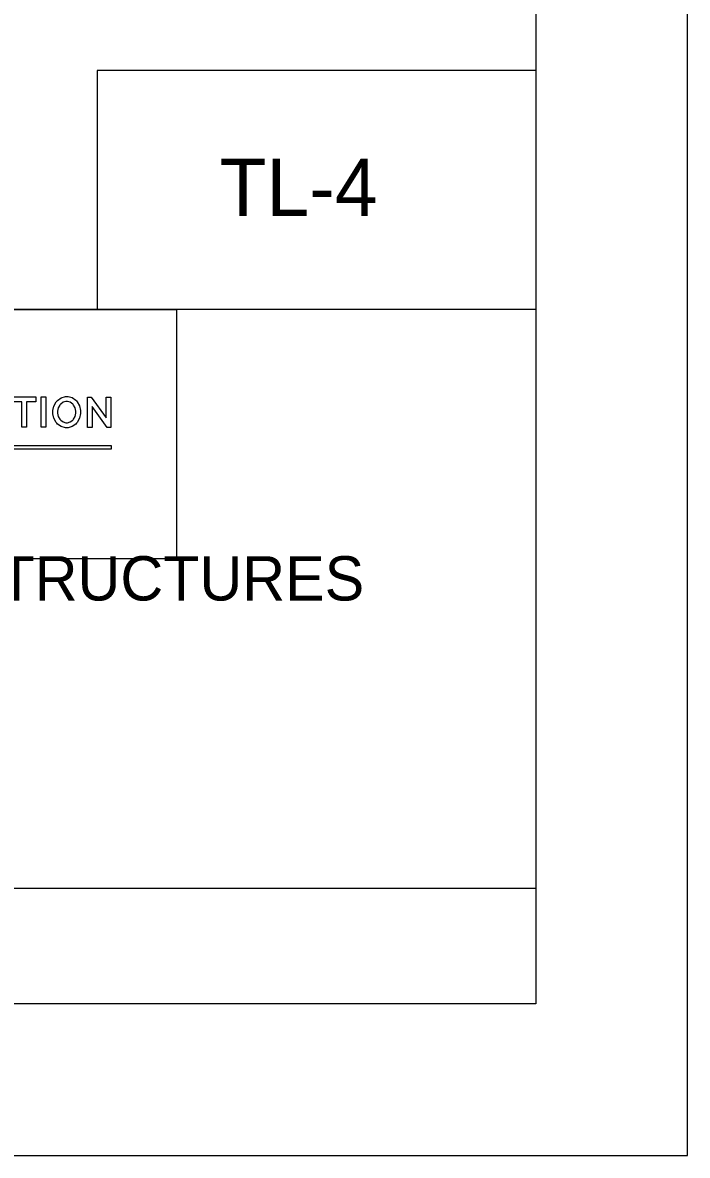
# Model space of a CAD drawing. Extents: x -27.4 to -18.9, y -4.2 to 6.8.
# Drawn here: x -20.305 to -18.916, y -4.191 to -1.823 of the extents above; entities that cross this region are included whole.
import ezdxf

# ---------------------------------------------------------------- set-up
doc = ezdxf.new("R2010")
doc.units = 0
for name, color, linetype in [('BORD-LINE', 7, 'Continuous'), ('Level 1', 7, 'Continuous'), ('MSHA-LOGO', 7, 'Continuous'), ('TTLB-TEXT', 7, 'Continuous'), ('USER-CLIP', 7, 'Continuous'), ('USER-LINE', 7, 'Continuous')]:
    doc.layers.add(name, color=color, linetype=linetype)

msp = doc.modelspace()

# ---------------------------------------------------------------- linework, layer by layer
at = {"layer": 'BORD-LINE'}
for p, q in [((-19.2324, -2.4232), (-23.7053, -2.4232)), ((-23.7053, -3.6322), (-19.2324, -3.6322))]:
    msp.add_line(p, q, dxfattribs=at)
msp.add_lwpolyline([(-26.6066, 6.4791), (-19.2324, 6.4791), (-19.2324, -3.874), (-26.6066, -3.874)], close=True, dxfattribs=at)
at = {"layer": 'Level 1'}
for p, q in [((-19.2324, -1.9232), (-20.1491, -1.9232)), ((-20.1491, -1.9232), (-20.1491, -2.4232))]:
    msp.add_line(p, q, dxfattribs=at)
at = {"layer": 'MSHA-LOGO'}
for points in [[(-20.3255, -2.6055), (-20.2774, -2.6055), (-20.2774, -2.6157), (-20.2964, -2.6157), (-20.2964, -2.669), (-20.3062, -2.669), (-20.3062, -2.6157), (-20.3252, -2.6157), (-20.3252, -2.6055)], [(-20.2659, -2.6055), (-20.2561, -2.6055), (-20.2561, -2.669), (-20.2659, -2.669)], [(-20.2332, -2.6144), (-20.2318, -2.6129), (-20.2239, -2.6073), (-20.2154, -2.6049), (-20.2126, -2.6049), (-20.2098, -2.6049), (-20.2013, -2.6071), (-20.1934, -2.6125), (-20.192, -2.6141), (-20.1906, -2.6156), (-20.1856, -2.6245), (-20.1834, -2.6342), (-20.1834, -2.6374), (-20.1834, -2.6406), (-20.1856, -2.6502), (-20.1906, -2.6592), (-20.192, -2.6608), (-20.1934, -2.6624), (-20.2013, -2.6677), (-20.2098, -2.67), (-20.2126, -2.67), (-20.2154, -2.67), (-20.2239, -2.6677), (-20.2318, -2.6624), (-20.2332, -2.6608), (-20.2346, -2.6592), (-20.2395, -2.6504), (-20.2417, -2.6407), (-20.2417, -2.6374), (-20.2417, -2.6343), (-20.2397, -2.6248), (-20.2347, -2.616)], [(-20.226, -2.6532), (-20.2251, -2.6543), (-20.2199, -2.658), (-20.2144, -2.6595), (-20.2126, -2.6595), (-20.2108, -2.6595), (-20.2053, -2.658), (-20.2001, -2.6543), (-20.1992, -2.6532), (-20.1983, -2.6522), (-20.195, -2.6463), (-20.1936, -2.6397), (-20.1936, -2.6374), (-20.1936, -2.6352), (-20.195, -2.6285), (-20.1983, -2.6226), (-20.1992, -2.6217), (-20.2001, -2.6206), (-20.2053, -2.6169), (-20.2108, -2.6154), (-20.2126, -2.6154), (-20.2144, -2.6154), (-20.2198, -2.6169), (-20.225, -2.6206), (-20.226, -2.6217), (-20.2269, -2.6226), (-20.2301, -2.6285), (-20.2315, -2.6352), (-20.2315, -2.6374), (-20.2315, -2.6397), (-20.2301, -2.6463), (-20.2269, -2.6522)], [(-20.1281, -2.6694), (-20.1595, -2.6259), (-20.1595, -2.6694), (-20.169, -2.6694), (-20.169, -2.6059), (-20.1615, -2.6059), (-20.1301, -2.6493), (-20.1301, -2.6059), (-20.1206, -2.6059), (-20.1206, -2.6694)], [(-22.2362, -2.7073), (-20.1195, -2.7073), (-20.1195, -2.7152), (-22.2362, -2.7152)]]:
    msp.add_lwpolyline(points, close=True, dxfattribs=at)
at = {"layer": 'USER-CLIP'}
msp.add_lwpolyline([(-18.9155, 6.8091), (-27.4155, 6.8091), (-27.4155, -4.1909), (-18.9155, -4.1909)], close=True, dxfattribs=at)
at = {"layer": 'USER-LINE'}
msp.add_lwpolyline([(-19.9833, -2.9439), (-22.9545, -2.9439), (-22.9545, -2.4232), (-19.9833, -2.4232)], close=True, dxfattribs=at)

# ---------------------------------------------------------------- texts
at = {"layer": 'BORD-LINE'}
msp.add_text('HDVBARREIRA', height=6e-12, rotation=180, dxfattribs=at).set_placement((-19.2324, -2.4232))
at = {"layer": 'TTLB-TEXT'}
for s, height, p in [('TL-4', 0.12, (-19.893, -2.2275)), ('STANDARDS FOR HIGHWAYS AND INCIDENTAL STRUCTURES', 0.09269, (-23.3095, -3.0312))]:
    msp.add_text(s, height=height, dxfattribs=at).set_placement(p)

doc.saveas('drawing.dxf')
